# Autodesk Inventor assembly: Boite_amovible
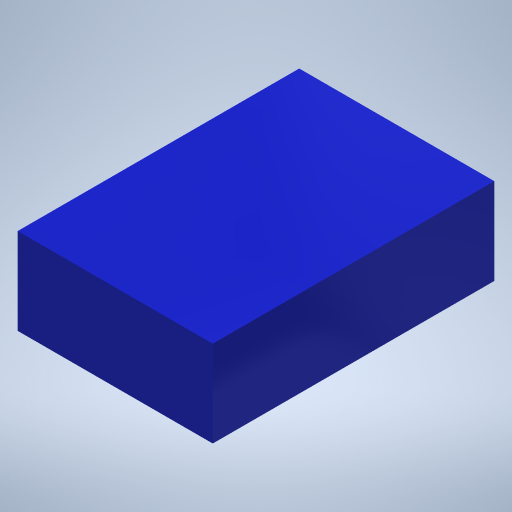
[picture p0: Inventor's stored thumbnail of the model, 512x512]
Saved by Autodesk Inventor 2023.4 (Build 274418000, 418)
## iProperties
Part Number: Boite_amovible
Material: Générique
Document SubType Name: Assembly
Designer: ficho
Author: ficho
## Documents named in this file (4)
- D:\travail\année 2019-2020\réforme\avant février\IT\Boite_amovible.iam
- D:\travail\année 2019-2020\réforme\avant février\IT\face_amov_vis.ipt
- D:\travail\année 2019-2020\réforme\avant février\IT\Cote_amov_vis.ipt
- D:\travail\année 2019-2020\réforme\avant février\IT\dessus_amov_vis.ipt
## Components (6 placed, 3 different names)
1. face_amov_vis:1 — Affleurement:1, Affleurement:2, Placage:1, Affleurement:4, Affleurement:5, Affleurement:6, Placage:2
2. face_amov_vis:2 — Affleurement:1, Affleurement:2, Placage:1, Affleurement:3, Affleurement:7, Affleurement:9
3. Cote_amov_vis:1 — Affleurement:3, Affleurement:8
4. Cote_amov_vis:2 — Affleurement:4, Affleurement:5, Affleurement:6
5. dessus_amov_vis:1 — Affleurement:7
6. dessus_amov_vis:2 — Placage:2, Affleurement:8, Affleurement:9
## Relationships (11: Flush 9, Mate 2)
- Affleurement:1 [Flush]: face_amov_vis:1 ↔ face_amov_vis:2
- Affleurement:2 [Flush]: face_amov_vis:1 ↔ face_amov_vis:2
- Placage:1 [Mate]: face_amov_vis:1 ↔ face_amov_vis:2
- Affleurement:3 [Flush]: face_amov_vis:2 ↔ Cote_amov_vis:1
- Affleurement:4 [Flush]: face_amov_vis:1 ↔ Cote_amov_vis:2
- Affleurement:5 [Flush]: face_amov_vis:1 ↔ Cote_amov_vis:2
- Affleurement:6 [Flush]: face_amov_vis:1 ↔ Cote_amov_vis:2
- Affleurement:7 [Flush]: face_amov_vis:2 ↔ dessus_amov_vis:1
- Placage:2 [Mate]: face_amov_vis:1 ↔ dessus_amov_vis:2
- Affleurement:8 [Flush]: Cote_amov_vis:1 ↔ dessus_amov_vis:2
- Affleurement:9 [Flush]: face_amov_vis:2 ↔ dessus_amov_vis:2
